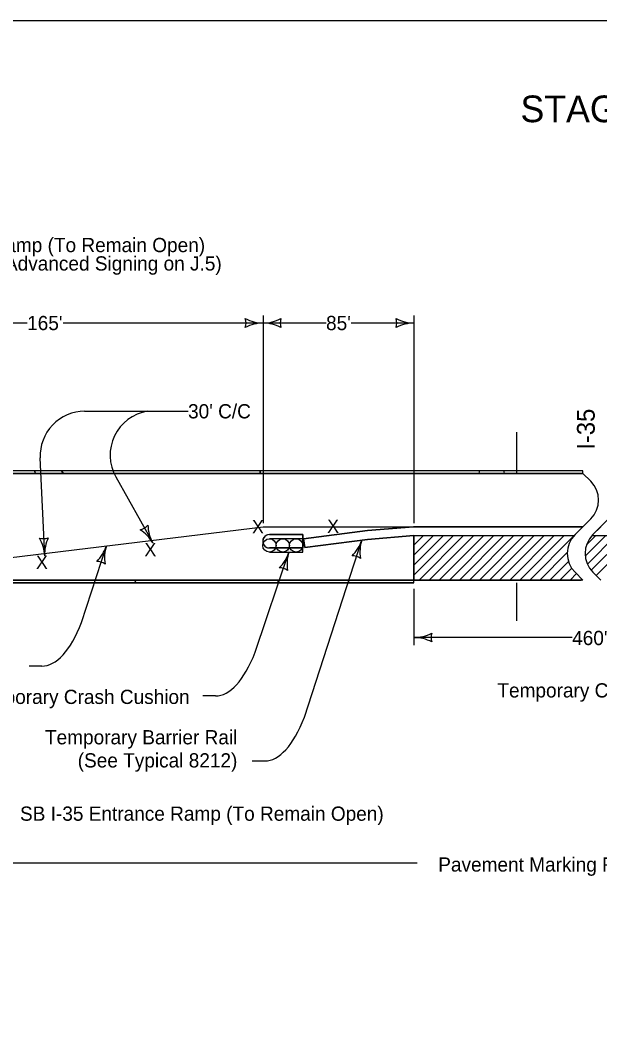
# Model space of a CAD drawing. Extents: x -2134934 to -2122394, y -2139046 to -2137036.
# Drawn here: x -2129313 to -2128661, y -2138183 to -2137036 of the extents above; entities that cross this region are included whole.
import ezdxf

# ---------------------------------------------------------------- set-up
doc = ezdxf.new("R2010")
doc.units = 0
for name, color, linetype in [('Barrier', 7, 'Continuous'), ('BridgeSuperStructureExisting', 7, 'Continuous'), ('Default', 7, 'Continuous'), ('dsnCellsNorthArrow', 7, 'Continuous'), ('DsnShtInsideBorder', 7, 'Continuous'), ('DsnShtPlotIdentification', 7, 'Continuous'), ('DsnShtPlotShape', 7, 'Continuous')]:
    doc.layers.add(name, color=color, linetype=linetype)

msp = doc.modelspace()

# ---------------------------------------------------------------- linework, layer by layer
at = {"layer": 'BridgeSuperStructureExisting'}
for p, q in [((-2129039.8, -2137367.6), (-2129039.8, -2137601.1)), ((-2128870.1, -2137367.6), (-2128870.1, -2137601.1)), ((-2129305.2, -2137376.2), (-2129530.1, -2137376.2)), ((-2129039.8, -2137376.2), (-2129264.7, -2137376.2)), ((-2128969, -2137376.2), (-2129039.8, -2137376.2)), ((-2128870.1, -2137376.2), (-2128940.9, -2137376.2)), ((-2129240.5, -2137475.4), (-2129124.2, -2137475.4)), ((-2128754.7, -2137498.8), (-2128754.7, -2137545.2)), ((-2129285.4, -2137637.7), (-2129290.5, -2137527.7)), ((-2128680.1, -2137545.2), (-2130182.6, -2137545.2)), ((-2129205.4, -2137549.2), (-2129163.9, -2137623.4)), ((-2128680.1, -2137545.2), (-2128671.3, -2137553.9)), ((-2128671.3, -2137553.9), (-2128680.1, -2137545.2)), ((-2128671.3, -2137596.4), (-2128688.9, -2137613.9)), ((-2128651.3, -2137596.4), (-2128668.9, -2137613.9)), ((-2129530.1, -2137665.2), (-2129039.8, -2137605.2)), ((-2129039.8, -2137605.2), (-2128870.7, -2137605.2)), ((-2128870.7, -2137605.2), (-2128922.2, -2137609.5)), ((-2128922.2, -2137609.5), (-2128870.7, -2137605.2)), ((-2128922.2, -2137609.5), (-2128870.7, -2137605.2)), ((-2128680.1, -2137605.2), (-2128870.7, -2137605.2)), ((-2128870.7, -2137605.2), (-2128680.1, -2137605.2)), ((-2128870.7, -2137605.2), (-2128680.1, -2137605.2)), ((-2128688.9, -2137613.9), (-2128680.1, -2137605.2)), ((-2128660.1, -2137605.2), (-2128668.9, -2137613.9)), ((-2129032.7, -2137614.1), (-2128995.2, -2137614.1)), ((-2128995.2, -2137618.8), (-2129032.7, -2137618.8)), ((-2128995.2, -2137614.1), (-2128995.2, -2137629.1)), ((-2128995.2, -2137633.8), (-2128995.2, -2137618.8)), ((-2128922.2, -2137609.5), (-2128994.2, -2137618.8)), ((-2128994.2, -2137618.8), (-2128922.2, -2137609.5)), ((-2128994.2, -2137618.8), (-2128922.2, -2137609.5)), ((-2128994.2, -2137618.8), (-2128992.9, -2137628.7)), ((-2128992.9, -2137628.7), (-2128994.2, -2137618.8)), ((-2128992.9, -2137628.7), (-2128994.2, -2137618.8)), ((-2128993.3, -2137819.5), (-2128928.9, -2137620.3)), ((-2128992.9, -2137628.7), (-2128922.4, -2137619.5)), ((-2128922.4, -2137619.5), (-2128992.9, -2137628.7)), ((-2128922.4, -2137619.5), (-2128992.9, -2137628.7)), ((-2128922.4, -2137619.5), (-2128870.3, -2137615.2)), ((-2128870.3, -2137615.2), (-2128922.4, -2137619.5)), ((-2128870.1, -2137615.2), (-2128922.4, -2137619.5)), ((-2128870.3, -2137615.2), (-2128690.1, -2137615.2)), ((-2128870.3, -2137615.2), (-2128690.1, -2137615.2)), ((-2128825.6, -2137615.2), (-2128870.1, -2137659.7)), ((-2128870.1, -2137615.2), (-2128870.1, -2137665.2)), ((-2128836.9, -2137615.2), (-2128870.1, -2137648.4)), ((-2128848.2, -2137615.2), (-2128870.1, -2137637.1)), ((-2128859.5, -2137615.2), (-2128870.1, -2137625.8)), ((-2128870.1, -2137665.2), (-2128870.1, -2137615.2)), ((-2128814.3, -2137615.2), (-2128864.3, -2137665.2)), ((-2128802.9, -2137615.2), (-2128852.9, -2137665.2)), ((-2128791.6, -2137615.2), (-2128841.6, -2137665.2)), ((-2128780.3, -2137615.2), (-2128830.3, -2137665.2)), ((-2128769, -2137615.2), (-2128819, -2137665.2)), ((-2128757.7, -2137615.2), (-2128807.7, -2137665.2)), ((-2128746.4, -2137615.2), (-2128796.4, -2137665.2)), ((-2128735.1, -2137615.2), (-2128785.1, -2137665.2)), ((-2128723.8, -2137615.2), (-2128773.8, -2137665.2)), ((-2128712.4, -2137615.2), (-2128762.4, -2137665.2)), ((-2128701.1, -2137615.2), (-2128751.1, -2137665.2)), ((-2128691.3, -2137616.6), (-2128739.8, -2137665.2)), ((-2128654.4, -2137615.2), (-2128677.5, -2137638.3)), ((-2128665.7, -2137615.2), (-2128676.1, -2137625.6)), ((-2128643.1, -2137615.2), (-2128675.1, -2137647.2)), ((-2128631.8, -2137615.2), (-2128670.8, -2137654.2)), ((-2128670.1, -2137615.2), (-2128470.5, -2137615.2)), ((-2128670.1, -2137615.2), (-2128470.1, -2137615.2)), ((-2128620.4, -2137615.2), (-2128665.3, -2137660)), ((-2129243.9, -2137712.8), (-2129216.1, -2137626.7)), ((-2128995.2, -2137629.1), (-2129032.7, -2137629.1)), ((-2129048.7, -2137746.4), (-2129010.8, -2137633.8)), ((-2129032.7, -2137633.8), (-2128995.2, -2137633.8)), ((-2128697.7, -2137634.3), (-2128728.5, -2137665.2)), ((-2128696.3, -2137644.3), (-2128717.2, -2137665.2)), ((-2128692.6, -2137651.9), (-2128705.9, -2137665.2)), ((-2130182.6, -2137665.2), (-2128870.1, -2137665.2)), ((-2128687.3, -2137657.9), (-2128694.6, -2137665.2)), ((-2128688.9, -2137656.4), (-2128680.1, -2137665.2)), ((-2128668.9, -2137656.4), (-2128660.1, -2137665.2)), ((-2128870.1, -2137675.2), (-2128870.1, -2137738.5)), ((-2128754.7, -2137668.2), (-2128754.7, -2137710.9)), ((-2128692.2, -2137729.8), (-2128870.1, -2137729.8)), ((-2129288.6, -2137762), (-2129302.8, -2137762)), ((-2129093.4, -2137795.5), (-2129107.7, -2137795.5)), ((-2129038, -2137868.7), (-2129052.2, -2137868.7)), ((-2128866.5, -2137983.3), (-2129530.1, -2137983.3))]:
    msp.add_line(p, q, dxfattribs=at)
for points in [[(-2128680.1, -2137605.2), (-2128680.1, -2137605.2), (-2128671.3, -2137596.4)], [(-2128690.1, -2137615.2), (-2128690.1, -2137615.2)], [(-2128680.1, -2137665.2), (-2128870.1, -2137665.2)]]:
    msp.add_lwpolyline(points, dxfattribs=at)
for centre in [(-2129032.7, -2137626.3), (-2129032.7, -2137626.3), (-2129017.7, -2137626.3), (-2129017.7, -2137626.3), (-2129002.7, -2137626.3), (-2129002.7, -2137626.3)]:
    msp.add_circle(centre, 7.5, dxfattribs=at)
for centre, radius, start, end in [((-2129240.5, -2137525.4), 50, 90, 182.6154), ((-2129161.7, -2137524.8), 50.1, 99.6171, 209.1999), ((-2128692.5, -2137575.2), 30, 315, 45), ((-2128692.5, -2137575.2), 30, 315, 45), ((-2129032.7, -2137621.6), 7.5, 89.9996, 270), ((-2128667.7, -2137635.2), 30, 135, 225), ((-2128667.7, -2137635.2), 30, 135, 138.2713), ((-2128647.7, -2137635.2), 30, 135, 225), ((-2128647.7, -2137635.2), 30, 135, 138.1884), ((-2128870.1, -2137687.4), 42.5, 270, 298.0725), ((-2128870.1, -2137772.3), 42.5, 61.9275, 90), ((-2128834.5, -2137729.8), 16.4, 162.2666, 197.7334)]:
    msp.add_arc(centre, radius, start, end, dxfattribs=at)
for centre in [(-2129288.6, -2137549.1), (-2129093.4, -2137582.6), (-2129038, -2137655.7)]:
    msp.add_ellipse(centre, major_axis=(0, -212.9), ratio=0.328743, start_param=0, end_param=0.693162, dxfattribs=at)
at = {"layer": 'Default'}
msp.add_lwpolyline([(-2130232, -2137035.9), (-2127097, -2137035.9), (-2127097, -2139045.9), (-2130232, -2139045.9)], close=True, dxfattribs=at)
at = {"layer": 'DsnShtInsideBorder'}
for p, q in [((-2128995.2, -2137614.1), (-2129032.7, -2137614.1)), ((-2128995.2, -2137629.1), (-2128995.2, -2137614.1)), ((-2129032.7, -2137629.1), (-2128995.2, -2137629.1))]:
    msp.add_line(p, q, dxfattribs=at)
msp.add_arc((-2129032.7, -2137621.6), 7.5, 90.0024, 269.9972, dxfattribs=at)
at = {"layer": 'DsnShtPlotIdentification'}
for p, q in [((-2128680.1, -2137542.2), (-2130182.6, -2137542.2)), ((-2128680.1, -2137545.2), (-2130182.6, -2137545.2)), ((-2129296.4, -2137542.2), (-2129329.6, -2137542.2)), ((-2129329.6, -2137545.2), (-2129296.2, -2137545.2)), ((-2129266.6, -2137542.2), (-2129296.4, -2137542.2)), ((-2129296.4, -2137542.2), (-2129296.2, -2137545.2)), ((-2129296.2, -2137545.2), (-2129296.4, -2137542.2)), ((-2129296.2, -2137545.2), (-2129264.4, -2137545.2)), ((-2129266.6, -2137542.2), (-2129264.4, -2137545.2)), ((-2129043.1, -2137542.2), (-2129266.6, -2137542.2)), ((-2129264.4, -2137545.2), (-2129266.6, -2137542.2)), ((-2129264.4, -2137545.2), (-2129043.1, -2137545.2)), ((-2128796.1, -2137542.2), (-2129043.1, -2137542.2)), ((-2129043.1, -2137542.2), (-2129043.1, -2137545.2)), ((-2129043.1, -2137545.2), (-2129043.1, -2137542.2)), ((-2129043.1, -2137545.2), (-2128797, -2137545.2)), ((-2128797, -2137545.2), (-2128768.2, -2137545.2)), ((-2128769.2, -2137542.2), (-2128796.1, -2137542.2)), ((-2128680.1, -2137542.2), (-2128769.2, -2137542.2)), ((-2128768.2, -2137545.2), (-2128680.1, -2137545.2)), ((-2128680.1, -2137545.2), (-2128680.1, -2137542.2)), ((-2130182, -2137665.2), (-2128682, -2137665.2)), ((-2129182.9, -2137665.2), (-2129475.9, -2137665.2)), ((-2129183.9, -2137668.2), (-2129182.9, -2137665.2)), ((-2129182.9, -2137665.2), (-2129183.9, -2137668.2)), ((-2129022.5, -2137665.2), (-2129182.9, -2137665.2)), ((-2129023.4, -2137668.2), (-2129022.5, -2137665.2)), ((-2129022.5, -2137665.2), (-2129023.4, -2137668.2)), ((-2128943.4, -2137665.2), (-2129022.5, -2137665.2)), ((-2128944.3, -2137668.2), (-2128943.4, -2137665.2)), ((-2128943.4, -2137665.2), (-2128944.3, -2137668.2)), ((-2128870.8, -2137665.2), (-2128943.4, -2137665.2)), ((-2128870.1, -2137665.2), (-2128870.8, -2137665.2)), ((-2128870.1, -2137668.2), (-2128870.1, -2137665.2)), ((-2128870.1, -2137668.2), (-2128870.1, -2137665.2)), ((-2129497.6, -2137668.2), (-2129183.9, -2137668.2)), ((-2129183.9, -2137668.2), (-2129023.4, -2137668.2)), ((-2129023.4, -2137668.2), (-2128944.3, -2137668.2)), ((-2128944.3, -2137668.2), (-2128870.1, -2137668.2))]:
    msp.add_line(p, q, dxfattribs=at)
for points in [[(-2130182.4, -2137545.2), (-2128872.4, -2137545.2)], [(-2128870.1, -2137665.2), (-2130182.6, -2137665.2)], [(-2128870.1, -2137668.2), (-2130182.6, -2137668.2)]]:
    msp.add_lwpolyline(points, dxfattribs=at)
for start, end in [(156.382, 168.6701), (156.382, 168.6701), (11.3299, 23.618), (11.3299, 23.618)]:
    msp.add_arc((-2128782.6, -2137548), 14.7, start, end, dxfattribs=at)
at = {"layer": 'DsnShtPlotShape'}
for centre, radius, start, end in [((-2129075.4, -2137376.2), 16.4, 342.2666, 17.7334), ((-2129039.8, -2137333.7), 42.5, 241.9275, 270), ((-2129039.8, -2137418.7), 42.5, 90, 118.0725), ((-2129039.8, -2137333.7), 42.5, 270, 298.0725), ((-2129039.8, -2137418.7), 42.5, 61.9275, 90), ((-2129004.2, -2137376.2), 16.4, 162.2666, 197.7334), ((-2128905.8, -2137376.2), 16.4, 342.2666, 17.7334), ((-2128870.1, -2137333.7), 42.5, 241.9275, 270), ((-2128870.1, -2137418.7), 42.5, 90, 118.0725), ((-2129181.5, -2137592.5), 16.4, 281.9035, 317.3702), ((-2129200.8, -2137644.5), 42.5, 29.6368, 57.7093), ((-2129126.9, -2137602.4), 42.5, 181.5643, 209.6368), ((-2129287.1, -2137602.2), 16.4, 254.8821, 290.3488), ((-2129327.9, -2137639.7), 42.5, 2.6154, 30.6879), ((-2129243, -2137635.8), 42.5, 154.5429, 182.6154), ((-2128969.3, -2137607.3), 42.5, 314.0124, 342.0849), ((-2128888.4, -2137633.4), 42.5, 162.0849, 190.1574), ((-2129256.5, -2137613.7), 42.5, 314.0124, 342.0849), ((-2129175.6, -2137639.8), 42.5, 162.0849, 190.1574), ((-2129051.2, -2137620.8), 42.5, 314.0124, 342.0849), ((-2128970.4, -2137646.9), 42.5, 162.0849, 190.1574), ((-2128939.8, -2137654.2), 16.4, 54.3516, 89.8183), ((-2129227, -2137660.6), 16.4, 54.3516, 89.8183), ((-2129021.8, -2137667.7), 16.4, 54.3516, 89.8183)]:
    msp.add_arc(centre, radius, start, end, dxfattribs=at)

# ---------------------------------------------------------------- texts
at = {"layer": 'Barrier'}
msp.add_text('STAGE 1', height=30, dxfattribs=at).set_placement((-2128750.3, -2137150.4))
at = {"layer": 'BridgeSuperStructureExisting'}
for s, height, p in [('SB I-35 Exit Ramp (To Remain Open)', 16, (-2129464.1, -2137296.5)), ('(See Exit Ramp Advanced Signing on J.5)', 16, (-2129485.9, -2137317.2)), ("165'", 16, (-2129305.2, -2137384.2)), ("85'", 16, (-2128969, -2137384.2)), ("30' C/C", 16, (-2129124.2, -2137483.4)), ('X', 15, (-2129052.3, -2137612.7)), ('X', 15, (-2128967.8, -2137612.1)), ("460'", 16, (-2128692.2, -2137738.3)), ('Temporary Crash Cushion', 16, (-2128776.3, -2137797.2)), ('Temporary Crash Cushion', 16, (-2129373.3, -2137804.5)), ('Temporary Barrier Rail', 16, (-2129285.1, -2137849.9)), ('(See Typical 8212)', 16, (-2129248.3, -2137875.9)), ('SB I-35 Entrance Ramp (To Remain Open)', 16, (-2129313.2, -2137935.8)), ('Pavement Marking Removal Limits', 16, (-2128842.8, -2137993))]:
    msp.add_text(s, height=height, dxfattribs=at).set_placement(p)
for p in [(-2129173.3, -2137638.4), (-2129295.3, -2137652.7)]:
    msp.add_text('X', height=15, rotation=359.9652, dxfattribs=at).set_placement(p)
at = {"layer": 'dsnCellsNorthArrow'}
msp.add_text('I-35', height=20, rotation=90, dxfattribs=at).set_placement((-2128666.8, -2137518.6))

doc.saveas('drawing.dxf')
